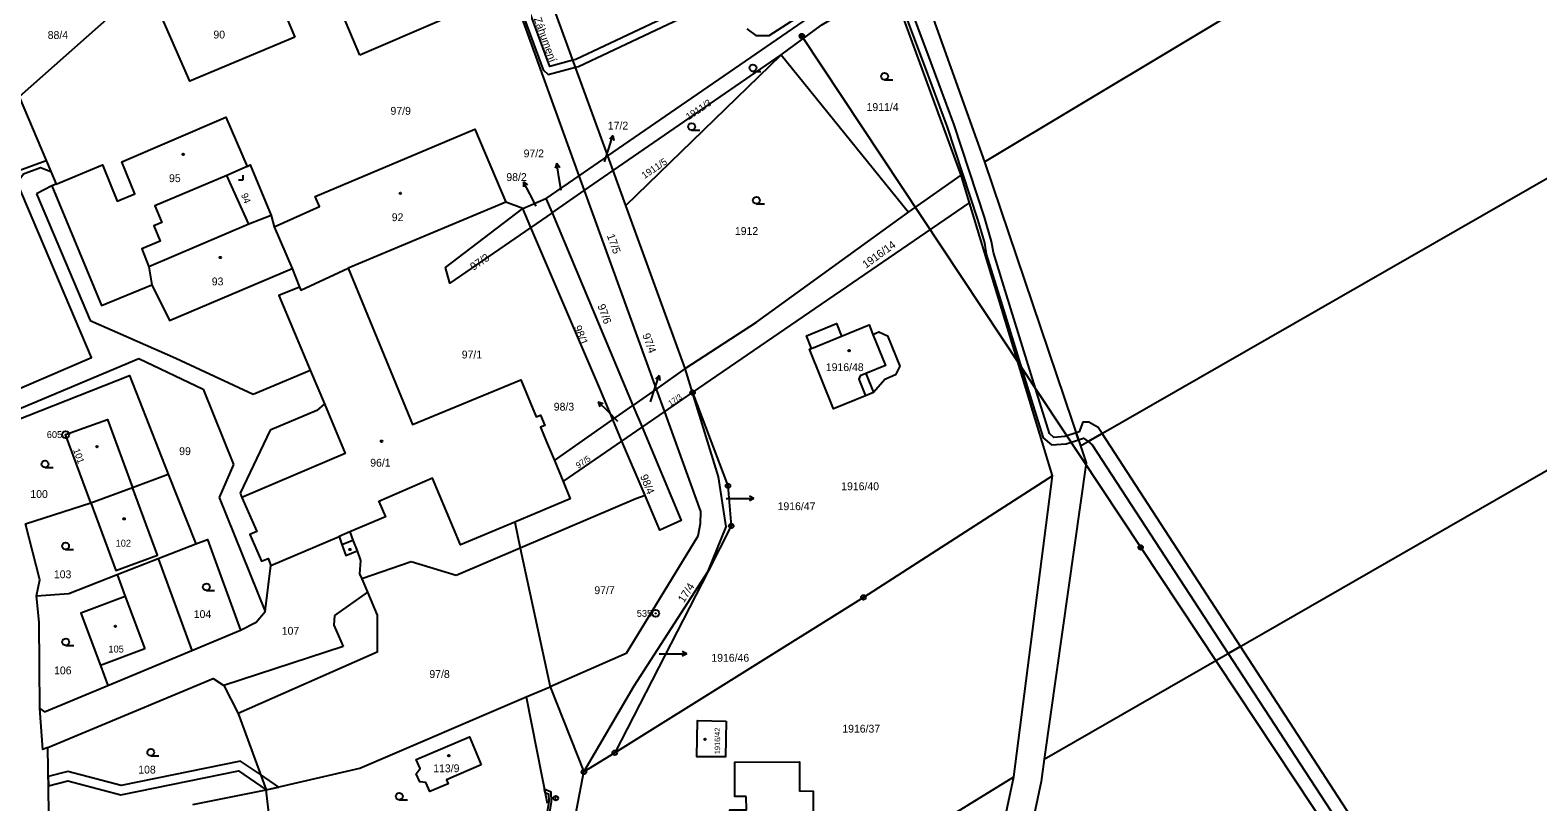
# Model space of a CAD drawing. Extents: x -504988 to -494607, y -1123820 to -1114018.
# Drawn here: x -497515.3 to -497187.9, y -1119655.4 to -1119487.8 of the extents above; entities that cross this region are included whole.
import ezdxf

# ---------------------------------------------------------------- set-up
doc = ezdxf.new("R2010")
doc.units = 0
for name, color, linetype in [('Hranice parcel', 7, 'Continuous'), ('Parcelní čísla', 7, 'Continuous'), ('Pop  PČ popisy', 7, 'Continuous'), ('Poz předměty', 7, 'Continuous'), ('Vnitřní kresba', 7, 'Continuous'), ('Věcná břemena k části', 7, 'Continuous'), ('Značky bodu BP', 7, 'Continuous'), ('Značky budov', 7, 'Continuous'), ('Značky kultur', 7, 'Continuous')]:
    doc.layers.add(name, color=color, linetype=linetype)

msp = doc.modelspace()

# ---------------------------------------------------------------- linework, layer by layer
at = {"layer": 'Hranice parcel'}
for p, q in [((-497389.87, -1119515.08), (-497404.54, -1119474.79)), ((-497322.99, -1119474.49), (-497308.05, -1119516.41)), ((-497490.57, -1119478.17), (-497517.69, -1119502.28)), ((-497313.08, -1119519.28), (-497328.33, -1119477.67)), ((-497389.87, -1119515.08), (-497343.95, -1119483.52)), ((-497388.7, -1119518.28), (-497352.23, -1119493.11)), ((-497385.94, -1119525.86), (-497352.23, -1119493.11)), ((-497352.23, -1119493.11), (-497324.55, -1119527.31)), ((-497517.69, -1119502.28), (-497511.85, -1119516.09)), ((-497511.85, -1119516.09), (-497510.84, -1119518.49)), ((-497389.87, -1119515.08), (-497396.14, -1119519.39)), ((-497388.7, -1119518.28), (-497389.87, -1119515.08)), ((-497308.05, -1119516.41), (-497287.17, -1119578.06)), ((-497510.84, -1119518.49), (-497509.69, -1119521.21)), ((-497396.14, -1119519.39), (-497403.29, -1119524.31)), ((-497396.14, -1119519.39), (-497394.97, -1119522.61)), ((-497394.97, -1119522.61), (-497388.7, -1119518.28)), ((-497385.94, -1119525.86), (-497388.7, -1119518.28)), ((-497324.55, -1119527.31), (-497313.08, -1119519.28)), ((-497311.27, -1119525.25), (-497313.08, -1119519.28)), ((-497408.32, -1119526.5), (-497403.29, -1119524.31)), ((-497403.29, -1119524.31), (-497401.98, -1119527.44)), ((-497401.98, -1119527.44), (-497394.97, -1119522.61)), ((-497394.97, -1119522.61), (-497379.37, -1119565.74)), ((-497412.04, -1119525.15), (-497446.25, -1119539.46)), ((-497408.32, -1119526.5), (-497412.04, -1119525.15)), ((-497406.57, -1119530.61), (-497408.32, -1119526.5)), ((-497401.98, -1119527.44), (-497406.57, -1119530.61)), ((-497373.03, -1119561.28), (-497385.94, -1119525.86)), ((-497371.44, -1119566.5), (-497311.27, -1119525.25)), ((-497293.26, -1119584.55), (-497311.27, -1119525.25)), ((-497462.98, -1119528), (-497462.36, -1119530.47)), ((-497462.36, -1119530.47), (-497458.42, -1119539.58)), ((-497489.59, -1119539.18), (-497488.9, -1119543.09)), ((-497458.42, -1119539.58), (-497456.86, -1119543.62)), ((-497373.03, -1119561.28), (-497379.37, -1119565.74)), ((-497371.44, -1119566.5), (-497373.03, -1119561.28)), ((-497379.37, -1119565.74), (-497384.42, -1119569.29)), ((-497379.37, -1119565.74), (-497377.57, -1119570.71)), ((-497377.57, -1119570.71), (-497371.44, -1119566.5)), ((-497388.79, -1119572.36), (-497384.42, -1119569.29)), ((-497384.42, -1119569.29), (-497382.43, -1119574.04)), ((-497401.47, -1119581.27), (-497388.79, -1119572.36)), ((-497386.8, -1119577.03), (-497388.79, -1119572.36)), ((-497382.43, -1119574.04), (-497377.57, -1119570.71)), ((-497399.59, -1119585.8), (-497386.8, -1119577.03)), ((-497386.8, -1119577.03), (-497382.43, -1119574.04)), ((-497401.47, -1119581.27), (-497399.59, -1119585.8)), ((-497493.09, -1119587.09), (-497485.32, -1119584.23)), ((-497485.32, -1119584.23), (-497479.35, -1119599.39)), ((-497293.26, -1119584.55), (-497334.35, -1119611)), ((-497301.66, -1119649.94), (-497293.26, -1119584.55)), ((-497502.15, -1119590.42), (-497493.09, -1119587.09)), ((-497516.37, -1119595.02), (-497502.15, -1119590.42)), ((-497487.5, -1119602.56), (-497479.35, -1119599.39)), ((-497496.45, -1119606.03), (-497487.5, -1119602.56)), ((-497487.5, -1119602.56), (-497480.22, -1119622.52)), ((-497368.08, -1119605.28), (-497388.35, -1119644.73)), ((-497334.35, -1119611), (-497388.35, -1119644.73)), ((-497480.22, -1119622.52), (-497469.66, -1119618.11)), ((-497498.45, -1119630.13), (-497480.22, -1119622.52)), ((-497407.59, -1119632.61), (-497402.41, -1119630.39)), ((-497407.59, -1119632.61), (-497403.06, -1119655.71)), ((-497402.41, -1119630.39), (-497395.06, -1119648.92)), ((-497470.18, -1119636.21), (-497464.09, -1119652.83)), ((-497511.18, -1119662.18), (-497511.51, -1119643.57)), ((-497388.35, -1119644.73), (-497395.06, -1119648.92)), ((-497327.77, -1119770.24), (-497301.66, -1119649.94)), ((-497326.62, -1119665.28), (-497301.66, -1119649.94)), ((-497480.03, -1119655.96), (-497464.09, -1119652.83)), ((-497460.28, -1119685.94), (-497464.09, -1119652.83))]:
    msp.add_line(p, q, dxfattribs=at)
for points in [[(-497287.17, -1119578.06), (-497169.39, -1119510.52), (-497051.6, -1119442.99), (-496883.73, -1119399.62), (-496715.86, -1119356.25), (-496588.85, -1119354.31), (-496461.84, -1119352.36), (-496271.46, -1119354.19), (-496081.08, -1119356.01), (-495890.7, -1119357.84)], [(-497308.05, -1119516.41), (-497183.35, -1119441.55), (-497073.98, -1119388.04), (-497009.04, -1119371.27)], [(-497295.06, -1119646.14), (-497162.9, -1119570.15), (-497030.73, -1119494.16), (-496869.61, -1119452.53), (-496708.48, -1119410.9), (-496585.08, -1119409.01), (-496461.68, -1119407.12), (-496276.03, -1119408.9), (-496090.37, -1119410.69), (-495904.72, -1119412.47)], [(-497443.72, -1119493.19), (-497455.45, -1119465.37), (-497437.92, -1119458.34), (-497426.32, -1119485.74), (-497443.72, -1119493.19)], [(-497417.89, -1119459.27), (-497416.38, -1119463.46), (-497396.14, -1119519.39)], [(-497457.83, -1119489.28), (-497480.66, -1119498.89), (-497489.46, -1119478.67), (-497466.44, -1119468.85), (-497457.83, -1119489.28)], [(-497352.23, -1119493.11), (-497343.35, -1119486.6), (-497328.33, -1119477.67)], [(-497509.69, -1119521.21), (-497499.65, -1119517.06), (-497496.4, -1119524.94), (-497492.56, -1119523.35), (-497495.45, -1119516.36), (-497472.83, -1119506.68), (-497468.17, -1119517.41)], [(-497462.36, -1119530.47), (-497452.45, -1119526.08), (-497453.4, -1119523.92), (-497418.74, -1119509.28), (-497412.04, -1119525.15)], [(-497540.12, -1119528.12), (-497535.42, -1119526.51), (-497518.6, -1119518.54), (-497511.85, -1119516.09)], [(-497526.19, -1119569.35), (-497521.88, -1119567.43), (-497502.02, -1119558.89), (-497518.12, -1119520.9), (-497516.76, -1119519.01), (-497513.1, -1119517.64), (-497510.84, -1119518.49)], [(-497468.17, -1119517.41), (-497472.58, -1119519.37), (-497488.28, -1119525.96), (-497486.72, -1119529.59), (-497488.44, -1119530.25), (-497487.09, -1119533.61), (-497491.07, -1119535.26), (-497489.59, -1119539.18)], [(-497468.17, -1119517.41), (-497467.55, -1119517), (-497462.98, -1119528)], [(-497509.69, -1119521.21), (-497510.61, -1119521.59), (-497499.86, -1119547.62), (-497488.9, -1119543.09)], [(-497406.57, -1119530.61), (-497424.15, -1119542.74), (-497425.15, -1119539.35), (-497408.32, -1119526.5)], [(-497401.98, -1119527.44), (-497385.34, -1119567.09), (-497384.42, -1119569.29)], [(-497373.03, -1119561.28), (-497357.58, -1119551.17), (-497324.55, -1119527.31)], [(-497462.98, -1119528), (-497467.87, -1119529.94), (-497489.59, -1119539.18)], [(-497388.79, -1119572.36), (-497391.6, -1119565.65), (-497406.57, -1119530.61)], [(-497488.9, -1119543.09), (-497485.06, -1119550.86), (-497458.42, -1119539.58)], [(-497456.86, -1119543.62), (-497456.55, -1119544.22), (-497446.25, -1119539.46)], [(-497446.25, -1119539.46), (-497432.25, -1119573.44), (-497408.73, -1119563.76), (-497405.4, -1119571.79), (-497404.47, -1119571.41), (-497403.56, -1119573.62), (-497404.48, -1119574), (-497403.16, -1119577.18), (-497401.47, -1119581.27)], [(-497456.86, -1119543.62), (-497461.31, -1119545.42), (-497454.51, -1119561.63), (-497451.43, -1119568.96), (-497446.91, -1119579.74), (-497469.33, -1119589.31), (-497466.07, -1119596.7), (-497467.59, -1119597.32), (-497465.07, -1119603.13), (-497463.65, -1119602.55), (-497463.05, -1119604.08)], [(-497345.63, -1119556.89), (-497346.74, -1119554.16), (-497340.21, -1119551.5), (-497339.1, -1119554.24), (-497333.11, -1119551.81), (-497332.28, -1119553.85), (-497331.03, -1119553.34), (-497329.1, -1119554.16), (-497326.42, -1119560.79), (-497327.37, -1119562.68), (-497329.68, -1119563.69), (-497332.14, -1119566.52), (-497333.89, -1119567.23), (-497340.83, -1119570.03), (-497346.09, -1119557.08), (-497345.63, -1119556.89)], [(-497526.85, -1119575.85), (-497493.75, -1119562.82), (-497485.32, -1119584.23)], [(-497368.08, -1119605.28), (-497364.13, -1119595.64), (-497365.84, -1119584.83), (-497371.44, -1119566.5)], [(-497371.44, -1119566.5), (-497363.76, -1119586.76), (-497363.04, -1119595.47), (-497368.08, -1119605.28)], [(-497502.15, -1119590.42), (-497507.62, -1119575.63), (-497498.51, -1119572.33), (-497493.09, -1119587.09)], [(-497377.57, -1119570.71), (-497369.75, -1119592.31), (-497369.82, -1119595.02), (-497370.31, -1119597.69), (-497385.88, -1119623.2), (-497402.41, -1119630.39)], [(-497382.43, -1119574.04), (-497373.95, -1119594.31), (-497378.59, -1119596.38), (-497381.77, -1119588.84), (-497386.8, -1119577.03)], [(-497287.17, -1119578.06), (-497285.93, -1119581.74), (-497295.06, -1119646.14)], [(-497410.09, -1119594.67), (-497421.83, -1119599.61), (-497427.91, -1119585.1), (-497439.58, -1119590.15), (-497438.15, -1119593.49), (-497445.89, -1119596.78), (-497445.22, -1119598.56), (-497444.32, -1119600.91)], [(-497399.59, -1119585.8), (-497398.02, -1119589.59), (-497410.09, -1119594.67)], [(-497502.15, -1119590.42), (-497496.74, -1119605.17), (-497487.68, -1119601.85), (-497493.09, -1119587.09)], [(-497513.92, -1119610.63), (-497513.2, -1119607.18), (-497516.37, -1119595.02)], [(-497410.09, -1119594.67), (-497408.88, -1119600.32), (-497402.41, -1119630.39)], [(-497479.35, -1119599.39), (-497476.82, -1119598.41), (-497469.66, -1119618.11)], [(-497463.05, -1119604.08), (-497448.24, -1119597.78), (-497447.61, -1119599.51), (-497446.76, -1119601.89), (-497444.32, -1119600.91)], [(-497444.32, -1119600.91), (-497443.61, -1119602.99), (-497443.79, -1119605.84), (-497443.32, -1119606.94), (-497442.05, -1119609.88), (-497439.93, -1119614.83), (-497439.99, -1119622.91), (-497470.18, -1119636.21)], [(-497513.92, -1119610.63), (-497506.94, -1119610.11), (-497496.45, -1119606.03)], [(-497496.45, -1119606.03), (-497494.67, -1119610.77), (-497504.35, -1119614.39), (-497500.07, -1119625.8), (-497498.45, -1119630.13)], [(-497469.66, -1119618.11), (-497466.25, -1119616.4), (-497464.28, -1119614.08), (-497463.05, -1119604.08)], [(-497395.06, -1119648.92), (-497384.14, -1119630.17), (-497368.08, -1119605.28)], [(-497513.2, -1119635.11), (-497513.39, -1119616.38), (-497513.92, -1119610.63)], [(-497511.51, -1119643.57), (-497475.58, -1119628.64), (-497473.28, -1119630.12), (-497470.18, -1119636.21)], [(-497513.2, -1119635.11), (-497512.21, -1119635.87), (-497498.45, -1119630.13)], [(-497464.09, -1119652.83), (-497443.73, -1119648.08), (-497407.59, -1119632.61)], [(-497511.51, -1119643.57), (-497512.61, -1119644.03), (-497513.2, -1119635.11)], [(-497364.18, -1119637.88), (-497364.32, -1119645.65), (-497370.56, -1119645.6), (-497370.37, -1119637.77), (-497364.18, -1119637.88)], [(-497417.35, -1119647.4), (-497424.89, -1119650.62), (-497424.54, -1119651.5), (-497428.5, -1119653.18), (-497429.38, -1119651.19), (-497430.72, -1119651.04), (-497431.46, -1119649.3), (-497430.63, -1119648.19), (-497431.47, -1119646.2), (-497419.91, -1119641.3), (-497417.35, -1119647.4)], [(-497405.68, -1119709.01), (-497404.18, -1119696.66), (-497395.06, -1119648.92)], [(-497359.78, -1119654.24), (-497362.29, -1119654.26), (-497362.28, -1119646.75), (-497348.25, -1119646.69), (-497348.23, -1119653.04), (-497345.27, -1119653.09), (-497345.26, -1119664.61), (-497364.27, -1119664.64), (-497364.26, -1119659.46), (-497363.35, -1119659.45), (-497363.37, -1119657.14), (-497359.76, -1119657.14), (-497359.78, -1119654.24)], [(-497295.06, -1119646.14), (-497295.74, -1119650.96), (-497318.23, -1119757.42)]]:
    msp.add_lwpolyline(points, dxfattribs=at)
at = {"layer": 'Pop  PČ popisy'}
for p, q in [((-497389.67, -1119513.51), (-497388.74, -1119510.66)), ((-497388.74, -1119510.66), (-497389.53, -1119511.45)), ((-497388.74, -1119510.66), (-497388.58, -1119511.76)), ((-497390.6, -1119516.37), (-497389.67, -1119513.51)), ((-497400.96, -1119516.68), (-497401.3, -1119517.74)), ((-497400.49, -1119519.64), (-497400.96, -1119516.68)), ((-497400.96, -1119516.68), (-497400.31, -1119517.59)), ((-497406.82, -1119523.36), (-497408.18, -1119520.69)), ((-497408.18, -1119520.69), (-497407.28, -1119521.35)), ((-497408.18, -1119520.69), (-497408.17, -1119521.81)), ((-497400.03, -1119522.61), (-497400.49, -1119519.64)), ((-497405.46, -1119526.04), (-497406.82, -1119523.36)), ((-497379.64, -1119565.64), (-497378.71, -1119562.79)), ((-497378.71, -1119562.79), (-497379.5, -1119563.58)), ((-497378.71, -1119562.79), (-497378.55, -1119563.89)), ((-497380.57, -1119568.5), (-497379.64, -1119565.64)), ((-497389.82, -1119570.64), (-497391.94, -1119568.52)), ((-497391.94, -1119568.52), (-497390.88, -1119568.87)), ((-497391.94, -1119568.52), (-497391.59, -1119569.58)), ((-497387.7, -1119572.77), (-497389.82, -1119570.64)), ((-497364.12, -1119589.51), (-497361.11, -1119589.52)), ((-497361.11, -1119589.52), (-497358.11, -1119589.52)), ((-497358.11, -1119589.52), (-497359.11, -1119589.02)), ((-497358.11, -1119589.52), (-497359.11, -1119590.02)), ((-497372.7, -1119623.26), (-497373.7, -1119622.76)), ((-497378.7, -1119623.25), (-497375.7, -1119623.26)), ((-497375.7, -1119623.26), (-497372.7, -1119623.26)), ((-497372.7, -1119623.26), (-497373.7, -1119623.76))]:
    msp.add_line(p, q, dxfattribs=at)
at = {"layer": 'Poz předměty'}
for p, q in [((-497347.73, -1119489.06), (-497274.12, -1119600.13)), ((-497274.12, -1119600.13), (-497203.38, -1119706.83))]:
    msp.add_line(p, q, dxfattribs=at)
for centre, radius in [((-497347.73, -1119489.06), 0.5), ((-497347.73, -1119489.06), 0.4), ((-497347.73, -1119489.06), 0.3), ((-497347.73, -1119489.06), 0.2), ((-497347.73, -1119489.06), 0.1), ((-497274.12, -1119600.13), 0.5), ((-497274.12, -1119600.13), 0.4), ((-497274.12, -1119600.13), 0.3), ((-497274.12, -1119600.13), 0.2), ((-497274.12, -1119600.13), 0.1)]:
    msp.add_circle(centre, radius, dxfattribs=at)
at = {"layer": 'Vnitřní kresba'}
for p, q in [((-497467.87, -1119529.94), (-497472.58, -1119519.37)), ((-497510.61, -1119521.59), (-497513.99, -1119523.3)), ((-497513.99, -1119523.3), (-497502.28, -1119550.87)), ((-497502.28, -1119550.87), (-497483.7, -1119559)), ((-497345.63, -1119556.89), (-497339.1, -1119554.24)), ((-497524.76, -1119572.94), (-497491.72, -1119559.08)), ((-497491.72, -1119559.08), (-497477.77, -1119565.74)), ((-497483.7, -1119559), (-497466.9, -1119566.84)), ((-497466.9, -1119566.84), (-497456.05, -1119562.27)), ((-497456.05, -1119562.27), (-497454.51, -1119561.63)), ((-497333.83, -1119562.33), (-497332.14, -1119566.52)), ((-497477.77, -1119565.74), (-497471.14, -1119582.13)), ((-497453.1, -1119570.41), (-497463.22, -1119574.67)), ((-497451.43, -1119568.96), (-497453.1, -1119570.41)), ((-497463.22, -1119574.67), (-497469.75, -1119588.33)), ((-497471.14, -1119582.13), (-497474.25, -1119589.32)), ((-497474.25, -1119589.32), (-497464.28, -1119614.08)), ((-497469.75, -1119588.33), (-497469.33, -1119589.31)), ((-497383.78, -1119589.61), (-497408.88, -1119600.32)), ((-497381.77, -1119588.84), (-497383.78, -1119589.61)), ((-497445.89, -1119596.78), (-497448.24, -1119597.78)), ((-497447.61, -1119599.51), (-497445.22, -1119598.56)), ((-497408.88, -1119600.32), (-497422.78, -1119606.21)), ((-497432.54, -1119603.3), (-497443.32, -1119606.94)), ((-497422.78, -1119606.21), (-497432.54, -1119603.3)), ((-497494.67, -1119610.77), (-497490.4, -1119622.18)), ((-497442.05, -1119609.88), (-497449.21, -1119614.95)), ((-497449.21, -1119614.95), (-497449.4, -1119617)), ((-497449.4, -1119617), (-497447.34, -1119621.67)), ((-497490.4, -1119622.18), (-497500.07, -1119625.8)), ((-497447.34, -1119621.67), (-497473.28, -1119630.12))]:
    msp.add_line(p, q, dxfattribs=at)
for points in [[(-497332.28, -1119553.85), (-497329.54, -1119560.59), (-497333.83, -1119562.33)], [(-497333.83, -1119562.33), (-497335.05, -1119562.83), (-497335.37, -1119563.56), (-497333.89, -1119567.23)]]:
    msp.add_lwpolyline(points, dxfattribs=at)
at = {"layer": 'Věcná břemena k části'}
for points in [[(-497411.81, -1119474.89), (-497403.93, -1119496.39), (-497402.84, -1119497.44), (-497396.88, -1119495.82), (-497396.23, -1119495.64), (-497365.23, -1119480.95)], [(-497365.57, -1119479.35), (-497396.79, -1119494.14), (-497397.43, -1119494.31), (-497402.48, -1119495.69), (-497410.31, -1119474.35)], [(-497326.91, -1119479.89), (-497321.14, -1119495.41), (-497316.15, -1119508.84), (-497309.53, -1119528.87), (-497308.07, -1119533.99), (-497307.68, -1119536.43), (-497304.8, -1119545.73), (-497297.52, -1119569.16), (-497295.29, -1119576.31), (-497293.49, -1119577.88), (-497290.3, -1119577.63), (-497287.62, -1119576.73), (-497288.13, -1119575.21), (-497290.62, -1119576.05), (-497292.95, -1119576.24), (-497293.89, -1119575.41), (-497296, -1119568.68), (-497303.28, -1119545.25), (-497306.12, -1119536.07), (-497306.51, -1119533.65), (-497308.01, -1119528.39), (-497314.63, -1119508.32), (-497319.64, -1119494.85), (-497325.41, -1119479.33)], [(-497359.69, -1119487.47), (-497357.74, -1119488.97), (-497354.8, -1119488.97), (-497344.34, -1119482.17)]]:
    msp.add_lwpolyline(points, dxfattribs=at)
for points in [[(-497288.13, -1119575.21), (-497287.62, -1119576.73), (-497286.53, -1119576.37), (-497285.56, -1119577.14), (-497282.52, -1119575.39), (-497283.37, -1119574.08), (-497285.35, -1119572.95), (-497286.69, -1119572.95), (-497287.5, -1119575)], [(-497284.65, -1119577.85), (-497255.1, -1119623.17), (-497252.47, -1119621.65), (-497282.52, -1119575.39), (-497285.56, -1119577.14)], [(-497209.78, -1119692.68), (-497207.28, -1119691.19), (-497209.05, -1119688.48), (-497252.47, -1119621.65), (-497255.1, -1119623.17), (-497211.59, -1119689.9)], [(-497511.4, -1119649.88), (-497511.36, -1119651.93), (-497507.18, -1119650.87), (-497495.65, -1119653.91), (-497470.07, -1119648.7), (-497464.09, -1119652.83), (-497461.32, -1119652.18), (-497465.31, -1119649.5), (-497469.65, -1119646.58), (-497495.59, -1119651.85), (-497507.18, -1119648.81)], [(-497402.66, -1119655.35), (-497405, -1119669.46), (-497411.67, -1119707.6), (-497411.08, -1119707.71), (-497404.4, -1119669.56), (-497402.06, -1119655.39), (-497402.15, -1119653.28), (-497403.66, -1119652.63), (-497403.52, -1119653.35), (-497402.73, -1119653.68)]]:
    msp.add_lwpolyline(points, close=True, dxfattribs=at)
at = {"layer": 'Značky bodu BP'}
for centre, radius in [((-497371.44, -1119566.5), 0.5), ((-497371.44, -1119566.5), 0.0303), ((-497507.62, -1119575.63), 0.75), ((-497507.62, -1119575.63), 0.03), ((-497363.76, -1119586.76), 0.5), ((-497363.76, -1119586.76), 0.0303), ((-497363.04, -1119595.47), 0.5), ((-497363.04, -1119595.47), 0.0303), ((-497334.35, -1119611), 0.5), ((-497334.35, -1119611), 0.0303), ((-497379.47, -1119614.46), 0.75), ((-497379.47, -1119614.46), 0.03), ((-497388.35, -1119644.73), 0.5), ((-497388.35, -1119644.73), 0.0303), ((-497395.06, -1119648.92), 0.5), ((-497395.06, -1119648.92), 0.0303), ((-497401.17, -1119654.6), 0.5), ((-497401.17, -1119654.6), 0.0303)]:
    msp.add_circle(centre, radius, dxfattribs=at)
at = {"layer": 'Značky budov'}
for centre in [(-497482.09, -1119514.74), (-497434.92, -1119523.21), (-497474.02, -1119537.16), (-497337.45, -1119557.38), (-497439.01, -1119577.07), (-497500.8, -1119578.27), (-497494.92, -1119593.93), (-497445.87, -1119600.59), (-497496.81, -1119617.29), (-497368.75, -1119641.83), (-497424.4, -1119645.37)]:
    msp.add_circle(centre, 0.175, dxfattribs=at)
at = {"layer": 'Značky kultur'}
for p, q in [((-497358.34, -1119496.72), (-497356.59, -1119496.72)), ((-497329.74, -1119498.55), (-497327.99, -1119498.55)), ((-497371.65, -1119509.5), (-497369.9, -1119509.5)), ((-497470.07, -1119520.3), (-497469.07, -1119520.3)), ((-497469.07, -1119520.3), (-497469.07, -1119519.3)), ((-497357.6, -1119525.47), (-497355.85, -1119525.47)), ((-497512.1, -1119582.79), (-497510.35, -1119582.79)), ((-497507.65, -1119600.58), (-497505.9, -1119600.58)), ((-497477.05, -1119609.49), (-497475.3, -1119609.49)), ((-497507.6, -1119621.45), (-497505.85, -1119621.45)), ((-497489.13, -1119645.42), (-497487.38, -1119645.42)), ((-497435.15, -1119654.95), (-497433.4, -1119654.95))]:
    msp.add_line(p, q, dxfattribs=at)
for centre in [(-497358.34, -1119495.97), (-497329.74, -1119497.8), (-497371.65, -1119508.75), (-497357.6, -1119524.72), (-497512.1, -1119582.04), (-497507.65, -1119599.83), (-497477.05, -1119608.74), (-497507.6, -1119620.7), (-497489.13, -1119644.67), (-497435.15, -1119654.2)]:
    msp.add_circle(centre, 0.75, dxfattribs=at)

# ---------------------------------------------------------------- texts
at = {"layer": 'Parcelní čísla'}
for s, height, p in [('88/4', 1.7, (-497511.52, -1119489.68)), ('90', 1.7, (-497475.53, -1119489.58)), ('97/9', 1.7, (-497437.06, -1119506.15)), ('1911/4', 1.7, (-497333.66, -1119505.33)), ('17/2', 1.7, (-497389.86, -1119509.36)), ('97/2', 1.7, (-497408.15, -1119515.4)), ('95', 1.7, (-497485.17, -1119520.78)), ('98/2', 1.7, (-497411.9, -1119520.54)), ('92', 1.7, (-497436.79, -1119529.26)), ('1912', 1.7, (-497362.26, -1119532.26)), ('93', 1.7, (-497475.89, -1119543.21)), ('97/1', 1.7, (-497421.59, -1119559.09)), ('1916/48', 1.7, (-497342.51, -1119561.83)), ('98/3', 1.7, (-497401.6, -1119570.42)), ('99', 1.7, (-497482.96, -1119580.08)), ('96/1', 1.7, (-497441.46, -1119582.59)), ('1916/40', 1.7, (-497339.17, -1119587.7)), ('100', 1.7, (-497515.29, -1119589.39)), ('1916/47', 1.7, (-497352.98, -1119592.04)), ('102', 1.5, (-497496.77, -1119599.97)), ('103', 1.7, (-497510.18, -1119606.83)), ('97/7', 1.7, (-497392.79, -1119610.28)), ('104', 1.7, (-497479.8, -1119615.47)), ('107', 1.7, (-497460.68, -1119619.1)), ('105', 1.5, (-497498.33, -1119622.97)), ('106', 1.7, (-497510.14, -1119627.7)), ('1916/46', 1.7, (-497367.37, -1119624.96)), ('97/8', 1.7, (-497428.62, -1119628.5)), ('1916/37', 1.7, (-497338.93, -1119640.36)), ('108', 1.7, (-497491.85, -1119649.25)), ('113/9', 1.7, (-497427.78, -1119648.97))]:
    msp.add_text(s, height=height, dxfattribs=at).set_placement(p)
for s, height, rotation, p in [('1911/3', 1.5, 34, (-497372.28, -1119507.36)), ('1911/5', 1.5, 34, (-497381.89, -1119520.14)), ('94', 1.5, 292, (-497469.57, -1119523.53)), ('17/5', 1.7, 290, (-497390.1, -1119532.38)), ('1916/14', 1.7, 36, (-497333.8, -1119539.6)), ('97/3', 1.7, 34, (-497419.05, -1119540.07)), ('97/6', 1.7, 290, (-497392.14, -1119547.62)), ('98/1', 1.7, 292, (-497397.3, -1119552.3)), ('97/4', 1.7, 290, (-497382.39, -1119553.97)), ('17/3', 1.2, 34, (-497376.23, -1119569.46)), ('101', 1.5, 290, (-497506.03, -1119578.94)), ('97/5', 1.3, 34, (-497396.26, -1119583.03)), ('98/4', 1.7, 292, (-497382.88, -1119584.67)), ('17/4', 1.7, 57, (-497373.35, -1119612.28)), ('1916/42', 1.2, 90, (-497365.46, -1119645.06))]:
    msp.add_text(s, height=height, rotation=rotation, dxfattribs=at).set_placement(p)
at = {"layer": 'Pop  PČ popisy'}
msp.add_text('Záhumení', height=1.7, rotation=290, dxfattribs=at).set_placement((-497405.98, -1119485.29))
at = {"layer": 'Značky bodu BP'}
for s, p in [('605', (-497511.72, -1119576.38)), ('535', (-497383.57, -1119615.21))]:
    msp.add_text(s, height=1.5, dxfattribs=at).set_placement(p)

doc.saveas('drawing.dxf')
